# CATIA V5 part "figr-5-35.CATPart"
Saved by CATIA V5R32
Part number: Part1
Bounding box of the stored display mesh (mm): x -39.481 to 85.69, y 0 to 131.399, z 0 to 44
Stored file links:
  D:\PROJECTS\Project 2022\CATIA V5 6R 2022\Resources\Part Files\c05_catia_v5_6r2022_prt\figr-5-35.CATPart
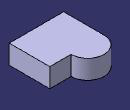
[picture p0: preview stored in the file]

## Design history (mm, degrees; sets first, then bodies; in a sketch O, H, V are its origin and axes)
Body1 (main body)
  Sketch1 on xy-plane, origin (0, 0, 0), H (1, 0, 0), V (0, 1, 0)
    point P1 (-39.4814, 0)
    line L1 (-39.4814, 0) -> (36.6898, 0)
    line L2 (36.6898, 0) -> (36.6898, 93.3015)
    arc A1 centre (-1.4186, 93.3015) radius 38.1084 from (36.6898, 93.3015) to (-39.4814, 95.1659) ccw
    line L3 (-39.4814, 95.1659) -> (-39.4814, 0)
    coincidence: P1 H
    horizontal: L1 H
    vertical: L2 V, L3 V
    tangency: A1 L2
  Pad1: profile Sketch1, direction (0, 0, 1), length 44
  Pad2: profile face of Pad1, direction along edge [face of Pad1 | face of Pad1] reversed, length -49, opposite side length -19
